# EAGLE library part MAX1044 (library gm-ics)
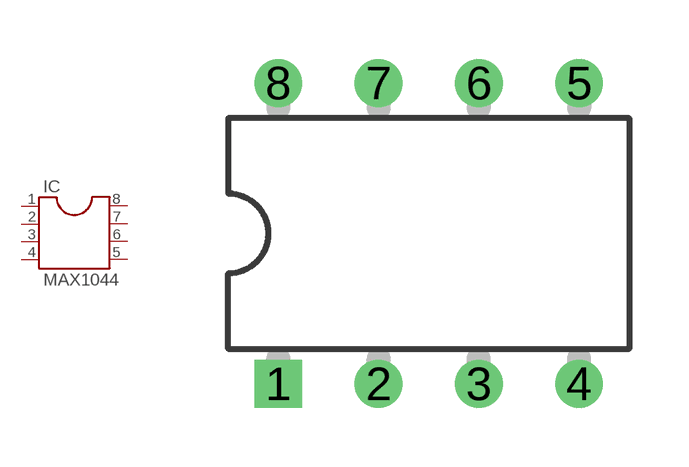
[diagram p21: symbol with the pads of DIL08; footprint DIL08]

Designator prefix IC

## MAX1044  [DIL08]
1  1  pas
2  2  pas
3  3  pas
4  4  pas
5  5  pas
6  6  pas
7  7  pas
8  8  pas

## Footprint DIL08 (pad centres in mm)
Dual In Line Package
drill 0.7 square: 1 -3.81,-3.81
drill 0.7 round: 2 -1.27,-3.81; 3 1.27,-3.81; 4 3.81,-3.81; 5 3.81,3.81; 6 1.27,3.81; 7 -1.27,3.81; 8 -3.81,3.81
